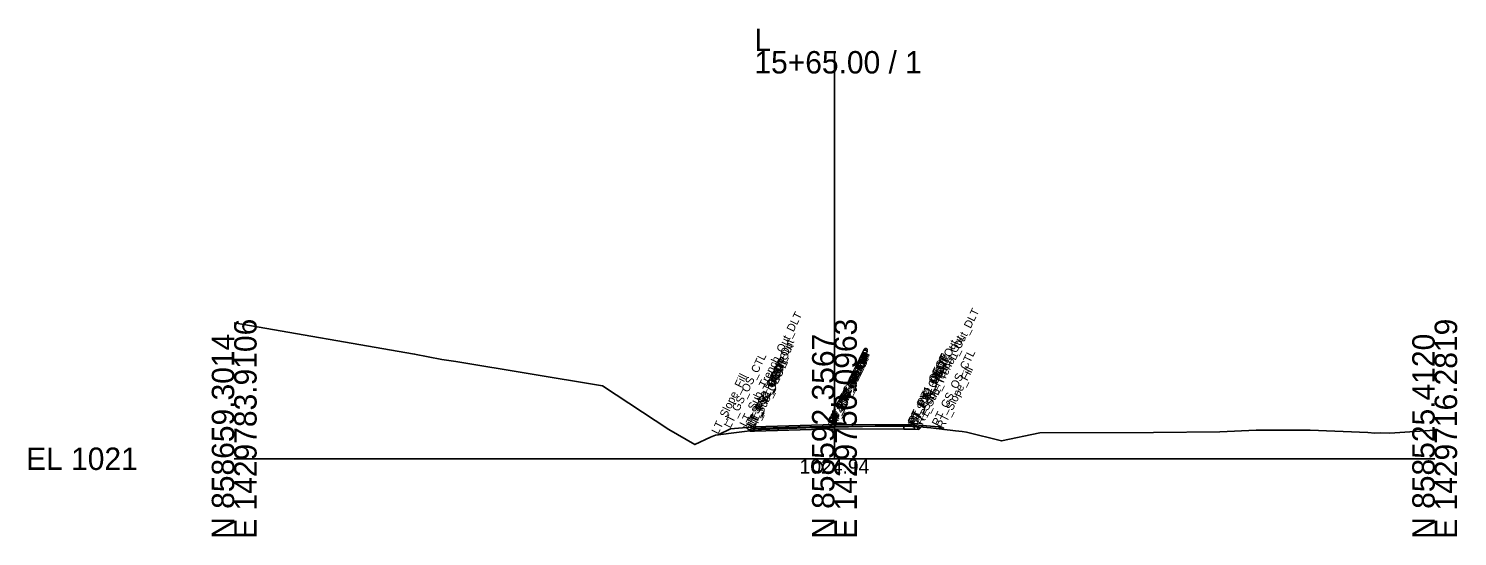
# Model space of a CAD drawing. Extents: x -26 to 2303, y -10 to 19558.
# Drawn here: x 2124.3 to 2302.8, y 7490.3 to 7553.7 of the extents above; entities that cross this region are included whole.
import ezdxf

# ---------------------------------------------------------------- set-up
doc = ezdxf.new("R2010")
doc.units = 0
for name, color, linetype in [('Default', 7, 'Continuous'), ('Exist CMT Pavement', 7, 'Continuous'), ('Exist Cross Section Cell', 7, 'Continuous'), ('Exist XS Center Line Elevation Label', 7, 'Continuous'), ('Exist XS Ground Line', 7, 'Continuous'), ('Prop CMT Conc Surface', 7, 'Continuous'), ('Prop CMT Pvmt Course 1', 7, 'Continuous'), ('Prop CMT Pvmt Course 2', 7, 'Continuous'), ('Prop CMT Pvmt Surface', 7, 'Continuous'), ('Prop CMT Pvmt Surface Shoulder', 7, 'Continuous'), ('Prop CMT Shld Paved Course 1', 7, 'Continuous'), ('Prop CMT Shld Paved Course 2', 7, 'Continuous'), ('Prop CMT Slope Grass', 7, 'Continuous'), ('Prop CMT Subgrade Earthwork', 7, 'Continuous'), ('Prop XS Dump Level', 7, 'Continuous')]:
    doc.layers.add(name, color=color, linetype=linetype)

msp = doc.modelspace()

# ---------------------------------------------------------------- linework, layer by layer
at = {"layer": 'Exist CMT Pavement'}
for p, q in [((2225, 7504.05), (2215.82, 7503.81)), ((2215.82, 7503.81), (2215.82, 7503.65)), ((2228.51, 7504.04), (2225, 7504.05))]:
    msp.add_line(p, q, dxfattribs=at)
msp.add_lwpolyline([(2215.82, 7503.65), (2222.55, 7503.89), (2224.63, 7503.93), (2225, 7503.94), (2228.51, 7504.04)], dxfattribs=at)
at = {"layer": 'Exist Cross Section Cell'}
for p, q in [((2225, 7500), (2225, 7550.9)), ((2150, 7500), (2225, 7500)), ((2225, 7500), (2300, 7500))]:
    msp.add_line(p, q, dxfattribs=at)
at = {"layer": 'Exist XS Ground Line'}
msp.add_lwpolyline([(2150, 7516.97), (2172.53, 7513.06), (2175.95, 7512.38), (2177.69, 7512.14), (2196.02, 7509.11), (2204.32, 7503.65), (2207.56, 7501.76), (2209.52, 7502.7), (2210.13, 7502.95), (2213.11, 7503.31), (2215.82, 7503.65), (2222.55, 7503.89), (2224.63, 7503.93), (2225, 7503.94), (2231.77, 7504.13), (2233.67, 7504.16), (2237.04, 7503.86), (2240.14, 7503.49), (2240.97, 7503.39), (2241.48, 7503.34), (2245.87, 7502.22), (2250.66, 7503.23), (2264.87, 7503.29), (2273.17, 7503.35), (2277.7, 7503.56), (2284.45, 7503.55), (2291.66, 7503.26), (2292.53, 7503.18), (2293.26, 7503.23), (2294.39, 7503.19), (2300, 7503.59)], dxfattribs=at)
at = {"layer": 'Prop CMT Conc Surface'}
for p, q in [((2215.82, 7503.48), (2215.82, 7503.81)), ((2233.67, 7504.16), (2233.67, 7503.69))]:
    msp.add_line(p, q, dxfattribs=at)
at = {"layer": 'Prop CMT Pvmt Course 1'}
for points in [[(2225, 7504.26), (2215, 7503.99)], [(2215, 7503.79), (2225, 7504.05)], [(2215, 7503.99), (2215, 7503.79)], [(2225, 7504.05), (2225, 7504.26)], [(2225, 7504.26), (2235, 7504.22)], [(2225, 7504.05), (2225, 7504.26)], [(2235, 7504.01), (2225, 7504.05)], [(2235, 7504.22), (2235, 7504.01)]]:
    msp.add_lwpolyline(points, dxfattribs=at)
msp.add_lwpolyline([(2225, 7504.05), (2225, 7504.14), (2225, 7504.14), (2225, 7504.05)], close=True, dxfattribs=at)
msp.add_lwpolyline([(2225, 7504.05), (2225, 7504.14), (2225, 7504.14), (2225, 7504.05)], close=True, dxfattribs=at)
at = {"layer": 'Prop CMT Pvmt Course 2'}
for points in [[(2225, 7504.05), (2215, 7503.79)], [(2215, 7503.79), (2215, 7503.45)], [(2225, 7504.05), (2235, 7504.01)], [(2235, 7504.01), (2235, 7503.68)], [(2215, 7503.45), (2215.82, 7503.48)], [(2235, 7503.68), (2233.67, 7503.69)]]:
    msp.add_lwpolyline(points, dxfattribs=at)
at = {"layer": 'Prop CMT Pvmt Surface'}
for points in [[(2225, 7504.26), (2215, 7503.99)], [(2225, 7504.26), (2235, 7504.22)]]:
    msp.add_lwpolyline(points, dxfattribs=at)
at = {"layer": 'Prop CMT Pvmt Surface Shoulder'}
for points in [[(2215, 7503.99), (2215, 7503.99)], [(2235, 7504.22), (2235, 7504.22)]]:
    msp.add_lwpolyline(points, dxfattribs=at)
at = {"layer": 'Prop CMT Shld Paved Course 1'}
for points in [[(2215, 7503.99), (2214.79, 7503.78)], [(2214.79, 7503.78), (2215, 7503.79)], [(2215, 7503.99), (2215, 7503.99)], [(2215, 7503.79), (2215, 7503.99)], [(2235, 7504.22), (2235, 7504.22)], [(2235, 7504.22), (2235.21, 7504.01)], [(2235, 7504.01), (2235, 7504.22)], [(2235.21, 7504.01), (2235, 7504.01)]]:
    msp.add_lwpolyline(points, dxfattribs=at)
at = {"layer": 'Prop CMT Shld Paved Course 2'}
for points in [[(2214.79, 7503.78), (2214.45, 7503.44)], [(2215, 7503.79), (2214.79, 7503.78)], [(2214.79, 7503.78), (2214.79, 7503.78)], [(2215, 7503.45), (2215, 7503.79)], [(2235, 7504.01), (2235.21, 7504.01)], [(2235, 7503.68), (2235, 7504.01)], [(2235.21, 7504.01), (2235.21, 7504.01)], [(2235.21, 7504.01), (2235.55, 7503.67)], [(2214.45, 7503.44), (2215, 7503.45)], [(2235.55, 7503.67), (2235, 7503.68)]]:
    msp.add_lwpolyline(points, dxfattribs=at)
at = {"layer": 'Prop CMT Slope Grass'}
for points in [[(2215, 7503.99), (2212, 7503.75), (2210.47, 7502.99)], [(2235, 7504.22), (2238, 7503.98), (2238.62, 7503.67)]]:
    msp.add_lwpolyline(points, dxfattribs=at)
at = {"layer": 'Prop CMT Subgrade Earthwork'}
for points in [[(2214.45, 7503.44), (2213.98, 7503.91)], [(2235.55, 7503.67), (2236.02, 7504.14)], [(2215, 7503.45), (2214.45, 7503.44)], [(2225, 7503.72), (2215, 7503.45)], [(2225, 7503.72), (2235, 7503.68)], [(2235, 7503.68), (2235.55, 7503.67)]]:
    msp.add_lwpolyline(points, dxfattribs=at)

# ---------------------------------------------------------------- texts
at = {"layer": 'Default'}
msp.add_text('-', height=0.0001, dxfattribs=at).set_placement((2150, 7500))
at = {"layer": 'Exist Cross Section Cell'}
for s, p in [('L', (2215, 7550.9)), ('15+65.00 / 1', (2215, 7548.1)), ('EL 1021', (2124, 7498.6))]:
    msp.add_text(s, height=2.8, dxfattribs=at).set_placement(p)
for s, p in [('E 1429783.9106', (2152.8, 7490)), ('E 1429750.0963', (2227.8, 7490)), ('E 1429716.2819', (2302.8, 7490)), ('N 858659.3014', (2150, 7490)), ('N 858592.3567', (2225, 7490)), ('N 858525.4120', (2300, 7490))]:
    msp.add_text(s, height=2.8, rotation=90, dxfattribs=at).set_placement(p)
at = {"layer": 'Exist XS Center Line Elevation Label'}
msp.add_text('1024.94', height=1.8, dxfattribs=at).set_placement((2220.65, 7498.14))
at = {"layer": 'Prop XS Dump Level'}
for s, p in [('LT_Sub_Trench_Out_DLT', (2213.98, 7503.91)), ('RT_Sub_Trench_Out_DLT', (2236.02, 7504.14)), ('LT_Sub_Trench_Out', (2214.45, 7503.44)), ('RT_PS2_Shelf_Out', (2235.21, 7504.01)), ('RT_Sub_Trench_Out', (2235.55, 7503.67)), ('LT_GS_OS_CTL', (2212, 7503.75)), ('LT_PS2_Shelf_Out', (2214.79, 7503.78)), ('LT_PV1_OEOT', (2215, 7503.99)), ('LT_PS1_OEOP', (2215, 7503.99)), ('RT_PV1_OEEOP', (2225, 7504.14)), ('RT_PV2_OEEOP', (2225, 7504.05)), ('LT_PV1_OEEOP', (2225, 7504.14)), ('LT_PV2_OEEOP', (2225, 7504.05)), ('RT_Sub_OEEOP', (2225, 7503.72)), ('RT_PV1_IEEOP', (2225, 7504.14)), ('RT_PV2_IEEOP', (2225, 7504.05)), ('LT_Sub_OEEOP', (2225, 7503.72)), ('LT_PV1_IEEOP', (2225, 7504.14)), ('LT_PV2_IEEOP', (2225, 7504.05)), ('RT_PV1_OEOT', (2235, 7504.22)), ('RT_PS1_OEOP', (2235, 7504.22)), ('RT_PV2_OEOT', (2235, 7504.01)), ('RT_PS2_OEOP', (2235.21, 7504.01)), ('RT_GS_OS_CTL', (2238, 7503.98)), ('LT_PS2_OEOP', (2214.79, 7503.78)), ('LT_PV2_OEOT', (2215, 7503.79)), ('LT_Sub_OEOT', (2215, 7503.45)), ('RT_Sub_OEOT', (2235, 7503.68)), ('RT_Slope_Fill', (2238.62, 7503.67)), ('LT_Slope_Fill', (2210.47, 7502.99)), ('PV1_PGL', (2225, 7504.26)), ('PV2_PGL', (2225, 7504.05))]:
    msp.add_text(s, height=1, rotation=63.5833, dxfattribs=at).set_placement(p)

doc.saveas('drawing.dxf')
